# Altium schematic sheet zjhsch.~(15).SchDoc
size A4
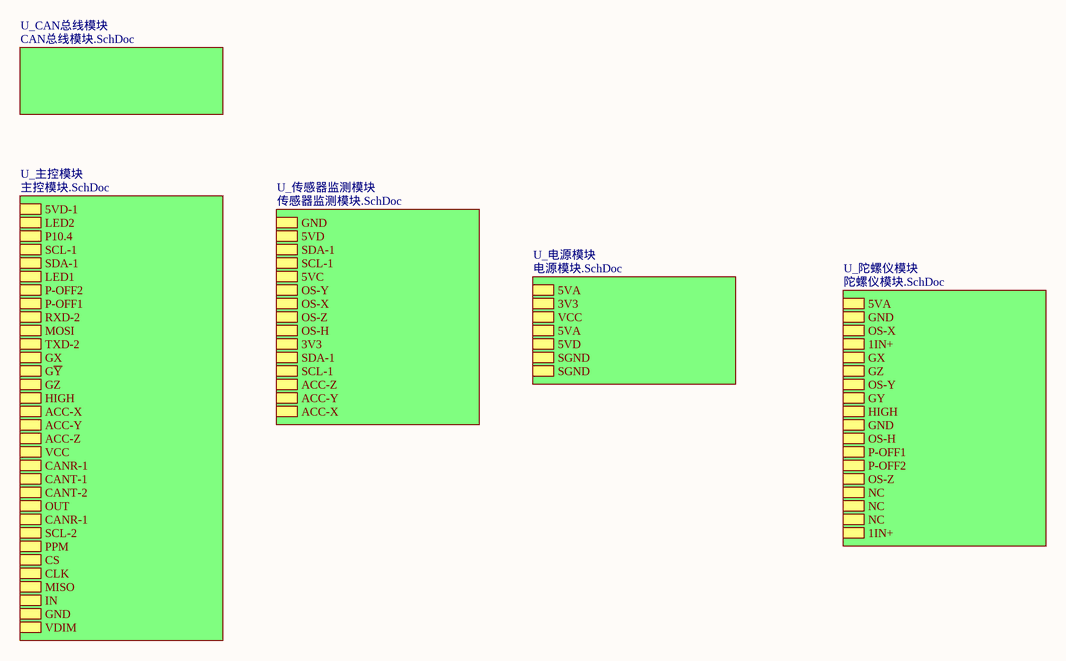
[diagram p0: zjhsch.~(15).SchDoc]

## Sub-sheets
U_CAN总线模块 = CAN总线模块.SchDoc: no entries
U_主控模块 = 主控模块.SchDoc: 5VD-1, LED2, P10.4, SCL-1, SDA-1, LED1, P-OFF2, P-OFF1, RXD-2, MOSI, TXD-2, GX, G~{Y}, GZ, HIGH, ACC-X, ACC-Y, ACC-Z, VCC, CANR-1, CANT-1, CANT-2, OUT, CANR-1, SCL-2, PPM, CS, CLK, MISO, IN, GND, VDIM
U_传感器监测模块 = 传感器监测模块.SchDoc: GND, 5VD, SDA-1, SCL-1, 5VC, OS-Y, OS-X, OS-Z, OS-H, 3V3, SDA-1, SCL-1, ACC-Z, ACC-Y, ACC-X
U_电源模块 = 电源模块.SchDoc: 5VA, 3V3, VCC, 5VA, 5VD, SGND, SGND
U_陀螺仪模块 = 陀螺仪模块.SchDoc: 5VA, GND, OS-X, 1IN+, GX, GZ, OS-Y, GY, HIGH, GND, OS-H, P-OFF1, P-OFF2, OS-Z, NC, NC, NC, 1IN+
